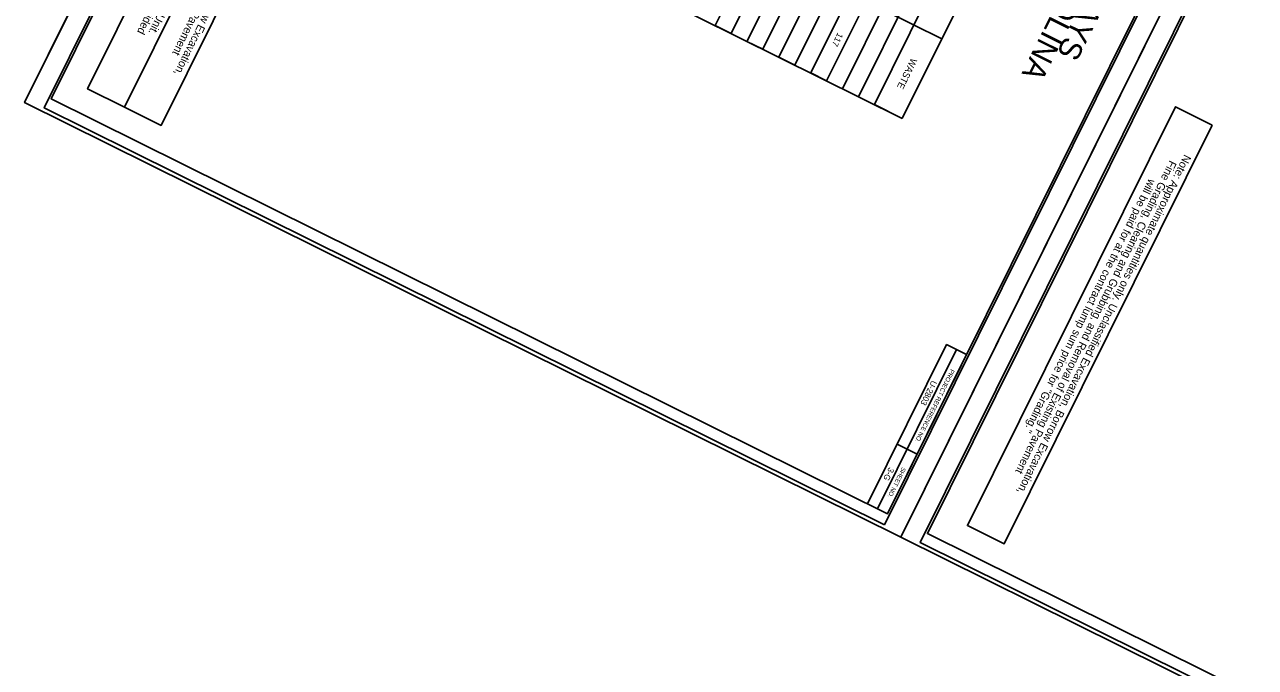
# Model space of a CAD drawing. Extents: x 2112338 to 2116552, y 435818 to 439065.
# Drawn here: x 2112338 to 2113722, y 436921 to 437644 of the extents above; entities that cross this region are included whole.
import ezdxf

# ---------------------------------------------------------------- set-up
doc = ezdxf.new("R2010")
doc.units = 0
for name, color, linetype in [('Old_Level_1', 7, 'Continuous'), ('Prop Grid Mask', 7, 'Continuous'), ('Prop XSC Text', 7, 'Continuous'), ('Sheet Cutting Line CELL', 7, 'Continuous'), ('Sheet Data Field CELL', 7, 'Continuous'), ('Sheet Plot Border Inside CELL', 7, 'Continuous'), ('Sheet Plot Border Outside CELL', 7, 'Continuous'), ('Sheet Summary Earthwork CELL', 7, 'Continuous'), ('Sheet Summary Guardrail CELL', 7, 'Continuous')]:
    doc.layers.add(name, color=color, linetype=linetype)

msp = doc.modelspace()

# ---------------------------------------------------------------- linework, layer by layer
at = {"layer": 'Prop Grid Mask'}
for points in [[(2112684.3, 438022.2), (2112450.4, 437551), (2112409.1, 437571.5), (2112642.9, 438042.7)], [(2112725.6, 438001.6), (2112491.7, 437530.5), (2112450.4, 437551), (2112684.3, 438022.2)], [(2113673.8, 437531), (2113439.9, 437059.8), (2113398.6, 437080.3), (2113632.5, 437551.5)]]:
    msp.add_lwpolyline(points, close=True, dxfattribs=at)
at = {"layer": 'Sheet Cutting Line CELL'}
for p, q in [((2113086.9, 439064.7), (2112338.2, 437556.3)), ((2113323.5, 437067.3), (2114072.2, 438575.7)), ((2114072.2, 438575.7), (2113323.5, 437067.3))]:
    msp.add_line(p, q, dxfattribs=at)
at = {"layer": 'Sheet Plot Border Inside CELL'}
for points in [[(2113305.4, 437081.3), (2114046.3, 438574), (2113101.2, 439043.1), (2112360.3, 437550.3)], [(2114086.5, 438554.1), (2113345.6, 437061.3), (2114290.7, 436592.2), (2115031.6, 438085)]]:
    msp.add_lwpolyline(points, close=True, dxfattribs=at)
at = {"layer": 'Sheet Plot Border Outside CELL'}
for points in [[(2113323.5, 437067.3), (2114072.2, 438575.7), (2113086.9, 439064.7), (2112338.2, 437556.3)], [(2114072.2, 438575.7), (2113323.5, 437067.3), (2114308.8, 436578.2), (2115057.5, 438086.7)]]:
    msp.add_lwpolyline(points, close=True, dxfattribs=at)
at = {"layer": 'Sheet Summary Earthwork CELL'}
for p, q in [((2113114.8, 437642.9), (2113448.2, 438314.7)), ((2113466.1, 438305.8), (2113132.7, 437634)), ((2113150.6, 437625.1), (2113484, 438296.9)), ((2113502, 438288), (2113168.5, 437616.2)), ((2113186.4, 437607.3), (2113519.9, 438279.1)), ((2113537.8, 438270.2), (2113204.4, 437598.4)), ((2113222.3, 437589.5), (2113555.7, 438261.3)), ((2113573.6, 438252.4), (2113240.2, 437580.6)), ((2113258.1, 437571.7), (2113591.5, 438243.5)), ((2113609.5, 438234.6), (2113276, 437562.8)), ((2113293.9, 437553.9), (2113627.4, 438225.7)), ((2113658.7, 438210.2), (2113325.3, 437538.4)), ((2112800.9, 437910.3), (2113369.7, 437628)), ((2113325.3, 437538.4), (2112756.5, 437820.7)), ((2113132.7, 437634), (2113114.8, 437642.9)), ((2113168.5, 437616.2), (2113150.6, 437625.1)), ((2113369.7, 437628), (2113325.3, 437538.4)), ((2113204.4, 437598.4), (2113186.4, 437607.3)), ((2113240.2, 437580.6), (2113222.3, 437589.5)), ((2113276, 437562.8), (2113258.1, 437571.7)), ((2113325.3, 437538.4), (2113293.9, 437553.9)), ((2113386.4, 437278.4), (2113297.4, 437099.2)), ((2113342, 437160.8), (2113319.6, 437171.9))]:
    msp.add_line(p, q, dxfattribs=at)
for points in [[(2113308.7, 437093.6), (2113975.5, 438437.2), (2113035, 438904), (2112368.1, 437560.4)], [(2113397.6, 437272.8), (2113308.7, 437093.6), (2113286.2, 437104.7), (2113375.2, 437283.9)]]:
    msp.add_lwpolyline(points, close=True, dxfattribs=at)
at = {"layer": 'Sheet Summary Guardrail CELL'}
msp.add_lwpolyline([(2114294, 436604.6), (2114960.8, 437948.2), (2114020.3, 438415), (2113353.5, 437071.4)], close=True, dxfattribs=at)

# ---------------------------------------------------------------- texts
at = {"layer": 'Old_Level_1'}
msp.add_text('117', height=7, rotation=243.6038, dxfattribs=at).set_placement((2113252.8, 437635.4))
at = {"layer": 'Prop XSC Text'}
for s, p in [('These earthwork quantities are based in part on subsurface data provided', (2112639.2, 437988)), ('Note: Earthwork quantities are calculated by the Roadway Design Unit.', (2112645.2, 437973.7)), ('Note: Approximate quantities only. Unclassified Excavation, Borrow Excavation,', (2112694.4, 437969.1)), (' Fine Grading, Clearing and Grubbing, and Removal of Existing Pavement', (2112679.5, 437965.5)), ('Note: Approximate quantities only. Unclassified Excavation, Borrow Excavation,', (2113642.6, 437498.5)), (' Fine Grading, Clearing and Grubbing, and Removal of Existing Pavement', (2113627.7, 437494.9)), (' will be paid for at the contract lump sum price for "Grading."', (2113604.2, 437474.1))]:
    msp.add_text(s, height=9, rotation=243.6038, dxfattribs=at).set_placement(p)
at = {"layer": 'Sheet Data Field CELL'}
for s, p in [('U-2803', (2113358.6, 437244.2)), ('3-G', (2113310.4, 437146.4))]:
    msp.add_text(s, height=6.75, rotation=243.6038, dxfattribs=at).set_placement(p)
at = {"layer": 'Sheet Summary Earthwork CELL'}
for s, height, p in [('STATE OF NORTH CAROLINA', 25, (2113668.9, 438011.3)), ('DIVISION OF HIGHWAYS', 25, (2113673.7, 437964.8)), ('WASTE', 7.75, (2113335.4, 437606.9)), ('PROJECT REFERENCE NO.', 5, (2113379.9, 437256.8)), ('SHEET NO.', 5, (2113325.1, 437146.5))]:
    msp.add_text(s, height=height, rotation=243.6038, dxfattribs=at).set_placement(p)

doc.saveas('drawing.dxf')
